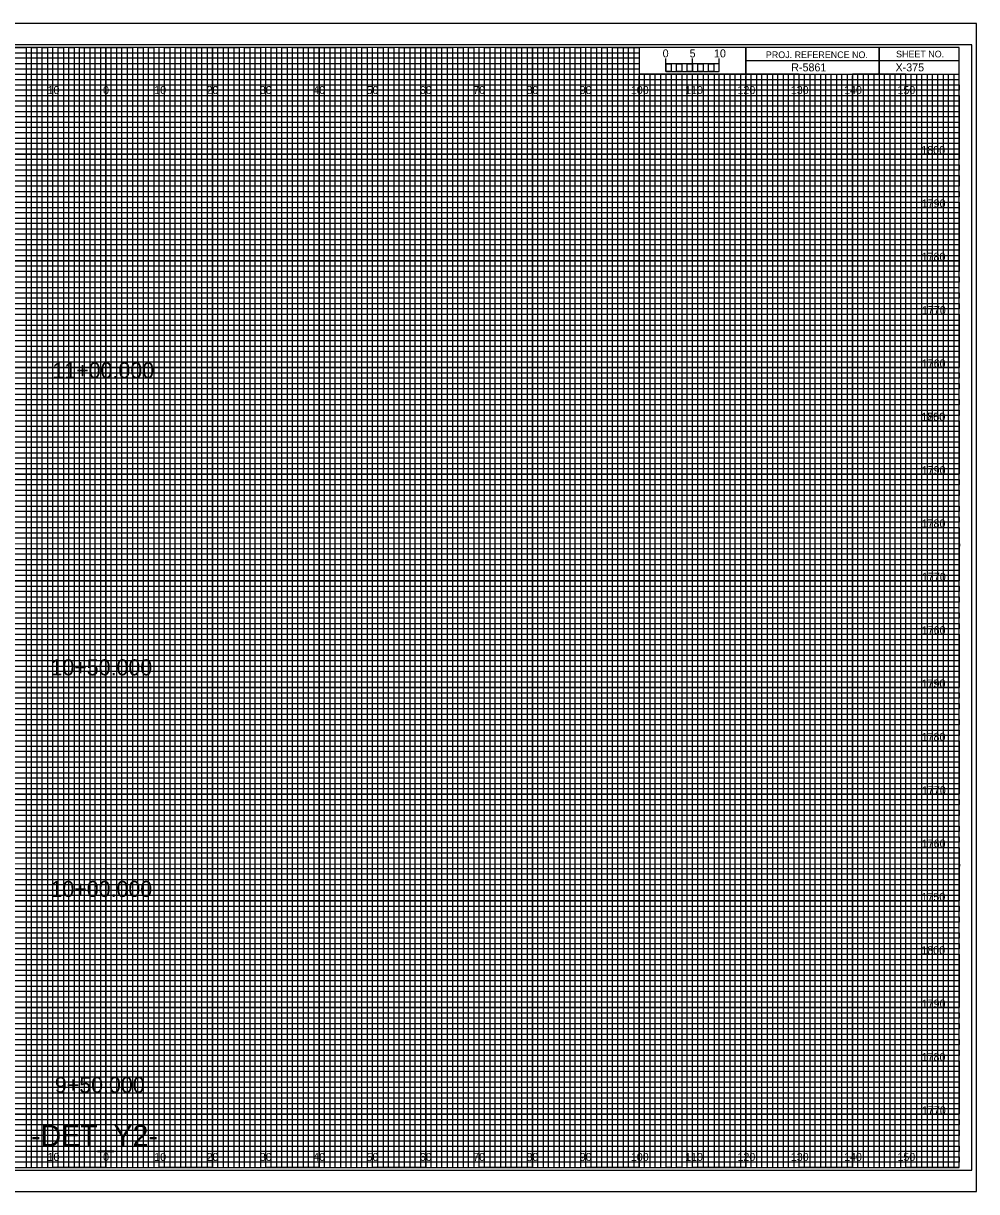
# Model space of a CAD drawing. Extents: x -13 to 323, y -5 to 874.
# Drawn here: x 144.5 to 323.3, y -4.5 to 214.5 of the extents above; entities that cross this region are included whole.
import ezdxf

# ---------------------------------------------------------------- set-up
doc = ezdxf.new("R2010")
doc.units = 0
for name, color, linetype in [('Prop Horizontal Alignment', 7, 'Continuous'), ('Prop XS Alignment Label', 7, 'Continuous'), ('Prop XS Bar Scale Labels', 7, 'Continuous'), ('Prop XS Earthwork Shape', 7, 'Continuous'), ('Prop XS Project Number', 7, 'Continuous'), ('Prop XS Sheet Number', 7, 'Continuous'), ('Raster_Level_0', 7, 'Continuous'), ('Scratch_Level_3', 7, 'Continuous'), ('Sheet Cross Section CELL', 7, 'Continuous'), ('Sheet Cross Section Grid Middle CELL', 7, 'Continuous'), ('Sheet Cross Section Grid Minor 1 CELL', 7, 'Continuous'), ('Sheet Cross Section Grid Minor 2 CELL', 7, 'Continuous'), ('Sheet Cross Section Scale CELL', 7, 'Continuous'), ('Sheet Cutting Line CELL', 7, 'Continuous'), ('Sheet DOT Grid CELL', 7, 'Continuous'), ('Sheet Plot Border Inside CELL', 7, 'Continuous'), ('Sheet Plot Border Outside CELL', 7, 'Continuous')]:
    doc.layers.add(name, color=color, linetype=linetype)

msp = doc.modelspace()

# ---------------------------------------------------------------- linework, layer by layer
at = {"layer": 'Prop XS Earthwork Shape'}
for p, q in [((150, 210), (140, 210)), ((150, 0), (150, 210)), ((170, 210), (160, 210)), ((160, 210), (160, 0)), ((170, 0), (170, 210)), ((190, 210), (180, 210)), ((180, 210), (180, 0)), ((190, 0), (190, 210)), ((210, 210), (200, 210)), ((200, 210), (200, 0)), ((210, 0), (210, 210)), ((230, 210), (220, 210)), ((220, 210), (220, 0)), ((230, 0), (230, 210)), ((250, 210), (240, 210)), ((240, 210), (240, 0)), ((250, 0), (250, 210)), ((260, 210), (260, 0)), ((270, 0), (270, 205)), ((290, 205), (280, 205)), ((280, 205), (280, 0)), ((290, 0), (290, 205)), ((310, 205), (300, 205)), ((300, 205), (300, 0)), ((310, 0), (310, 205)), ((160, 0), (150, 0)), ((180, 0), (170, 0)), ((200, 0), (190, 0)), ((220, 0), (210, 0)), ((240, 0), (230, 0)), ((260, 0), (250, 0)), ((280, 0), (270, 0)), ((300, 0), (290, 0)), ((320, 0), (310, 0)), ((320, 0), (320, 0))]:
    msp.add_line(p, q, dxfattribs=at)
for points in [[(0, 200), (320, 200), (320, 190), (0, 190)], [(0, 180), (320, 180), (320, 170), (0, 170)], [(0, 160), (320, 160), (320, 150), (0, 150)], [(0, 140), (320, 140), (320, 130), (0, 130)], [(0, 120), (320, 120), (320, 110), (0, 110)], [(0, 100), (320, 100), (320, 90), (0, 90)], [(0, 80), (320, 80), (320, 70), (0, 70)], [(0, 60), (320, 60), (320, 50), (0, 50)], [(0, 40), (320, 40), (320, 30), (0, 30)], [(0, 20), (320, 20), (320, 10), (0, 10)]]:
    msp.add_lwpolyline(points, dxfattribs=at)
at = {"layer": 'Sheet Cross Section CELL'}
for p, q in [((305, 210), (305, 205)), ((305, 205), (305, 210)), ((280, 207.5), (280, 205)), ((320, 207.49), (280, 207.49)), ((280, 205), (320, 205))]:
    msp.add_line(p, q, dxfattribs=at)
for points in [[(320, 210), (0, 210), (0, 0), (320, 0)], [(280, 210), (260, 210), (260, 205.03), (280, 205.03)], [(320, 210), (280, 210), (280, 205), (320, 205)]]:
    msp.add_lwpolyline(points, close=True, dxfattribs=at)
at = {"layer": 'Sheet Cross Section Grid Middle CELL'}
for points in [[(135, 210), (145, 210), (145, 0), (155, 0), (155, 210), (165, 210), (165, 0), (175, 0), (175, 210), (185, 210), (185, 0), (195, 0), (195, 210), (205, 210), (205, 0), (215, 0), (215, 210), (225, 210), (225, 0), (235, 0), (235, 210), (245, 210), (245, 0), (255, 0), (255, 210), (259.93, 210), (260, 210), (260, 205), (264.99, 205), (264.99, 0), (275, 0), (275, 205), (285, 205), (285, 0), (295, 0), (295, 205), (305, 205), (305, 0), (315, 0), (315, 205)], [(0, 205), (275, 205)], [(0, 185), (320, 185), (320, 195), (0, 195)], [(0, 165), (320, 165), (320, 175), (0, 175)], [(0, 145), (320, 145), (320, 155), (0, 155)], [(0, 125), (320, 125), (320, 135), (0, 135)], [(0, 105), (320, 105), (320, 115), (0, 115)], [(0, 85), (320, 85), (320, 95), (0, 95)], [(0, 65), (320, 65), (320, 75), (0, 75)], [(0, 45), (320, 45), (320, 55), (0, 55)], [(0, 25), (320, 25), (320, 35), (0, 35)], [(0, 5), (320, 5), (320, 15), (0, 15)]]:
    msp.add_lwpolyline(points, dxfattribs=at)
at = {"layer": 'Sheet Cross Section Grid Minor 1 CELL'}
for p, q in [((0, 209), (260, 209)), ((260, 209), (260, 207.98)), ((260, 207.98), (0, 207.98)), ((0, 207), (260, 207)), ((260, 205.89), (0, 205.89)), ((260, 207), (260, 205.89)), ((0, 204), (320, 204))]:
    msp.add_line(p, q, dxfattribs=at)
for points in [[(0, 203), (270, 203), (320, 203), (320, 202), (0, 202)], [(0, 201), (320, 201), (320, 199), (0, 199)], [(0, 198), (320, 198), (320, 197), (0, 196.98)], [(0, 196), (320, 196), (320, 194), (0, 194)], [(0, 193), (320, 193), (320, 192), (0, 192)], [(0, 191), (320, 191), (320, 189), (0, 189)], [(0, 188), (320, 188), (320, 187), (0, 187)], [(0, 186), (320, 186), (320, 184), (0, 184)], [(0, 183), (320, 183), (320, 182), (0, 182)], [(0, 181), (320, 181), (320, 179), (0, 179)], [(0, 178), (320, 178), (320, 177), (0, 177)], [(0, 176), (320, 176), (320, 173.95), (320, 173), (320, 172), (0, 172)], [(0, 174), (320, 174), (320, 173), (0, 173)], [(0, 171), (320, 171), (320, 169), (0, 169.03)], [(0, 169.03), (320, 169), (320, 168), (0, 168)], [(0, 167), (320, 167), (320, 166), (0, 166)], [(0, 164), (320, 164), (320, 163), (0, 163)], [(0, 162), (320, 162), (320, 161), (0, 161)], [(-0.07, 158.89), (320, 158.89), (320, 157.88), (-0.07, 157.88)], [(0, 157), (320, 157), (320, 156), (0, 156)], [(0, 154), (320, 154), (320, 153), (0, 153)], [(0, 152), (320, 152), (320, 151), (0, 151)], [(0, 149), (320, 149), (320, 148), (0, 148)], [(0, 147), (320, 147), (320, 146), (0, 146)], [(0, 144), (320, 144), (320, 143), (0, 143)], [(0, 142), (320, 142), (320, 141), (0, 141)], [(0, 139), (320, 139), (319.99, 137.98), (0, 138)], [(0, 137), (320, 137), (320, 136), (0, 136)], [(0, 134), (320, 134), (320, 133), (0, 133)], [(0, 132), (320, 132), (320, 131), (0, 131)], [(0, 129), (320, 129), (320, 128), (0, 128)], [(0, 127), (320, 127), (320, 126), (0, 126)], [(0, 124), (320, 124), (320, 123), (0, 123)], [(0, 122), (320, 122), (320, 121), (0, 121)], [(0, 119), (320, 119), (320, 118), (0, 118)], [(0, 116.99), (320.07, 116.91), (320, 116), (0, 116)], [(0, 114), (320, 114), (320, 113), (0, 113)], [(0, 112), (320, 112), (320, 111), (0, 111)], [(0, 109), (320, 109), (320, 108), (0, 108)], [(0, 107), (320, 107), (320, 106), (0, 106)], [(0, 104), (320, 104), (320, 103), (0, 103)], [(0, 102), (320, 102), (320, 101), (0, 101)], [(0, 99), (320, 99), (320, 98), (0, 98)], [(0, 97), (320, 97), (320, 96), (0, 96)], [(0, 94), (320, 94), (320, 93), (0, 93)], [(0, 92), (320, 92), (320, 91), (0, 91)], [(0, 89), (320, 89), (320, 88), (0, 88)], [(0, 87), (320, 87), (320, 86), (0, 86)], [(0, 84), (320, 84), (320, 83), (0, 83)], [(0, 82), (320, 82), (320, 81), (0, 81)], [(0, 79), (320, 79), (319.99, 77.98), (0, 78)], [(0, 77), (320, 77), (320, 76), (0, 76)], [(0, 74), (320, 74), (320, 73), (0, 73)], [(0, 72), (320, 72), (320, 71), (0, 71)], [(0, 69), (320, 69), (320, 68), (0, 68)], [(0, 67), (320, 67), (320, 66), (0, 66)], [(0, 64), (320, 64), (320, 63), (0, 63)], [(0, 62), (320, 62), (320, 61), (0, 61)], [(0, 59), (320, 59), (320, 58), (0, 58)], [(0, 56.99), (320.07, 56.91), (320, 56), (0, 56)], [(0, 54), (320, 54), (320, 53), (0, 53)], [(0, 52), (320, 52), (320, 51), (0, 51)], [(0, 49), (320, 49), (320, 48), (0, 48)], [(0, 47), (320, 47), (320, 46), (0, 46)], [(0, 44), (320, 44), (320, 43), (0, 43)], [(0, 42), (320, 42), (320, 41), (0, 41)], [(0, 39), (320, 39), (320, 38), (0, 38)], [(0, 37), (320, 37), (320, 36), (0, 36)], [(0, 34), (320, 34), (320, 33), (0, 33)], [(0, 32), (320, 32), (320, 31), (0, 31)], [(0, 29), (320, 29), (320, 28), (0, 28)], [(0, 27), (320, 27), (320, 26), (0, 26)], [(0, 24), (320, 24), (320, 23), (0, 23)], [(0, 22), (320, 22), (320, 21), (0, 21)], [(0, 19), (320, 19), (320, 18), (0, 18)], [(0, 17), (320, 17), (320, 16), (0, 16)], [(0, 14), (320, 14), (320, 13), (0, 13)], [(0, 12), (320, 12), (320, 11), (0, 11)], [(0, 9), (320, 9), (320, 8), (0, 8)], [(0, 7), (320, 7), (320, 6), (0, 6)], [(0, 4), (320, 4), (320, 3), (0, 3)], [(0, 2), (320, 2), (320, 1), (0, 1)]]:
    msp.add_lwpolyline(points, dxfattribs=at)
at = {"layer": 'Sheet Cross Section Grid Minor 2 CELL'}
for p, q in [((267, 205), (266.01, 205)), ((266.01, 205), (266.01, 0)), ((267, 0), (267, 205)), ((269, 205), (268, 205)), ((268, 205), (268, 0)), ((269, 0), (269, 205)), ((266.01, 0), (265, 0)), ((268, 0), (267, 0))]:
    msp.add_line(p, q, dxfattribs=at)
for points in [[(145, 0), (146, 0), (146, 210), (147, 210), (147, 0)], [(147, 0), (148, 0), (148, 210), (149, 210), (149, 0)], [(150, 0), (151, 0), (151, 210), (152, 210), (152, 0)], [(152, 0), (153, 0), (153, 210), (154, 210), (154, 0)], [(155, 0), (156, 0), (156, 210), (157, 210), (157, 0)], [(157, 0), (158, 0), (158, 210), (159, 210), (159, 0)], [(160, 0), (161, 0), (161, 210), (162, 210), (162, 0)], [(162, 0), (163, 0), (163, 210), (164, 210), (164, 0)], [(165, 0), (166, 0), (166, 210), (167, 210), (167, 0)], [(167, 0), (168, 0), (168, 210), (169, 210), (169, 0)], [(170, 0), (171, 0), (171, 210), (172, 210), (172, 0)], [(172, 0), (173, 0), (173, 210), (174, 210), (174, 0)], [(175, 0), (176, 0), (176, 210), (177, 210), (177, 0)], [(177, 0), (178, 0), (178, 210), (179, 210), (179, 0)], [(180, 0), (181, 0), (181, 210), (182, 210), (182, 0)], [(182, 0), (183, 0), (183, 210), (184, 210), (184, 0)], [(185, 0), (186, 0), (186, 210), (187, 210), (187, 0)], [(187, 0), (188, 0), (188, 210), (189, 210), (189, 0)], [(190, 0), (191, 0), (191, 210), (192, 210), (192, 0)], [(192, 0), (193, 0), (193, 210), (194, 210), (194, 0)], [(195, 0), (196, 0), (196, 210), (197, 210), (197, 0)], [(197, 0), (198, 0), (198, 210), (199, 210), (199, 0)], [(200, 0), (201, 0), (201, 210), (202, 210), (202, 0)], [(202, 0), (203, 0), (203, 210), (204, 210), (204, 0)], [(205, 0), (206, 0), (206, 210), (207, 210), (207, 0)], [(207, 0), (208, 0), (208, 210), (209, 210), (209, 0)], [(210, 0), (211, 0), (211, 210), (212, 210), (212, 0)], [(212, 0), (213, 0), (213, 210), (214, 210), (214, 0)], [(215, 0), (216, 0), (216, 210), (217, 210), (217, 0)], [(217, 0), (218, 0), (218, 210), (219, 210), (219, 0)], [(220, 0), (221, 0), (221, 210), (222, 210), (222, 0)], [(222, 0), (223, 0), (223, 210), (224, 210), (224, 0)], [(225, 0), (226, 0), (226, 210), (227, 210), (227, 0)], [(227, 0), (228, 0), (228, 210), (229, 210), (229, 0)], [(230, 0), (231, 0), (231, 210), (232, 210), (232, 0)], [(232, 0), (233, 0), (233, 210), (234, 210), (234, 0)], [(235, 0), (236, 0), (236, 210), (237, 210), (237, 0)], [(237, 0), (238, 0), (238, 210), (239, 210), (239, 0)], [(240, 0), (241, 0), (241, 210), (242, 210), (242, 0)], [(242, 0), (243, 0), (243, 210), (244, 210), (244, 0)], [(245, 0), (246, 0), (246, 210), (247, 210), (247, 0)], [(247, 0), (248, 0), (248, 210), (249, 210), (249, 0)], [(250, 0), (251, 0), (251, 210), (252, 210), (252, 0)], [(252, 0), (253, 0), (253, 210), (254, 210), (254, 0)], [(255, 0), (256, 0), (256, 210), (257, 210), (257, 0)], [(257, 0), (258, 0), (258, 210), (259, 210), (259, 0)], [(260, 0), (261, 0), (261, 205), (262.02, 205), (262.02, 0)], [(262, 0), (263, 0), (263, 205), (263.99, 205), (263.99, 0)], [(270, 0), (270.98, 0), (270.98, 205), (272, 205), (272, 0)], [(272, 0), (273, 0), (273, 205), (274.05, 205), (274.05, 0)], [(275, 0), (276, 0), (276, 205), (277, 205), (277, 0)], [(277, 0), (278, 0), (278, 205), (279, 205), (279, 0)], [(280, 0), (281, 0), (281, 205), (282, 205), (282, 0)], [(282, 0), (283, 0), (283, 205), (284, 205), (284, 0)], [(285, 0), (286, 0), (286, 205), (287, 205), (287, 0)], [(287, 0), (288, 0), (288, 205), (289, 205), (289, 0)], [(290, 0), (291, 0), (291, 205), (292, 205), (292, 0)], [(292, 0), (293, 0), (293, 205), (294, 205), (294, 0)], [(295, 0), (296, 0), (296, 205), (297, 205), (297, 0)], [(297, 0), (298, 0), (298, 205), (299, 205), (299, 0)], [(300, 0), (301, 0), (301, 205), (302, 205), (302, 0)], [(302, 0), (303, 0), (303, 205), (304, 205), (304, 0)], [(305, 0), (306, 0), (306, 205), (307, 205), (307, 0)], [(307, 0), (308, 0), (308, 205), (309, 205), (309, 0)], [(310, 0), (311, 0), (311, 205), (312, 205), (312, 0)], [(312, 0), (313, 0), (313, 205), (314, 205), (314, 0)], [(315, 0), (316, 0), (316, 205), (317, 205), (317, 0)], [(317, 0), (318, 0), (318, 205), (319, 205), (319, 0)]]:
    msp.add_lwpolyline(points, dxfattribs=at)
at = {"layer": 'Sheet Cross Section Scale CELL'}
for p, q in [((265, 205.49), (265, 207.9)), ((265, 206.9), (265, 207.9)), ((270, 205.49), (270, 207.9)), ((275, 205.49), (275, 207.9)), ((275, 206.9), (275, 207.9))]:
    msp.add_line(p, q, dxfattribs=at)
for points in [[(275, 206.9), (265, 206.9), (265, 205.49), (275, 205.49)], [(265, 206.9), (266, 206.9), (266, 205.49), (265, 205.49)], [(267, 206.9), (268, 206.9), (268, 205.49), (267, 205.49)], [(269, 206.9), (270, 206.9), (270, 205.49), (269, 205.49)], [(271, 206.9), (272, 206.9), (272, 205.49), (271, 205.49)], [(273, 206.9), (274, 206.9), (274, 205.49), (273, 205.49)]]:
    msp.add_lwpolyline(points, close=True, dxfattribs=at)
at = {"layer": 'Sheet Cutting Line CELL'}
for p, q in [((323.3, 214.5), (-13.4, 214.5)), ((-13.4, -4.5), (323.3, -4.5))]:
    msp.add_line(p, q, dxfattribs=at)
at = {"layer": 'Sheet DOT Grid CELL'}
for p, q in [((150, 0), (150, 210)), ((160, 0), (160, 210)), ((170, 0), (170, 210)), ((180, 0), (180, 210)), ((190, 0), (190, 210)), ((200, 0), (200, 210)), ((210, 0), (210, 210)), ((220, 0), (220, 210)), ((230, 0), (230, 210)), ((240, 0), (240, 210)), ((250, 0), (250, 210)), ((260, 0), (260, 204.69)), ((270, 0), (270, 204.69)), ((280, 0), (280, 204.69)), ((290, 0), (290, 204.69)), ((300, 0), (300, 204.69)), ((310, 0), (310, 204.69)), ((0, 200), (320, 200)), ((0, 190), (320, 190)), ((0, 180), (320, 180)), ((0, 170), (320, 170)), ((0, 160), (320, 160)), ((0, 150), (320, 150)), ((0, 140), (320, 140)), ((0, 130), (320, 130)), ((0, 120), (320, 120)), ((0, 110), (320, 110)), ((0, 100), (320, 100)), ((0, 90), (320, 90)), ((0, 80), (320, 80)), ((0, 70), (320, 70)), ((0, 60), (320, 60)), ((0, 50), (320, 50)), ((0, 40), (320, 40)), ((0, 30), (320, 30)), ((0, 20), (320, 20)), ((0, 10), (320, 10))]:
    msp.add_line(p, q, dxfattribs=at)
at = {"layer": 'Sheet Plot Border Inside CELL'}
msp.add_lwpolyline([(-10.8, -0.5), (322.4, -0.5), (322.4, 210.5), (-10.8, 210.5)], close=True, dxfattribs=at)
at = {"layer": 'Sheet Plot Border Outside CELL'}
msp.add_lwpolyline([(-13.4, -4.5), (323.3, -4.5), (323.3, 214.5), (-13.4, 214.5)], close=True, dxfattribs=at)

# ---------------------------------------------------------------- texts
at = {"layer": 'Prop Horizontal Alignment'}
for s, p in [('11+00.000', (149.95, 147.96)), ('10+50.000', (149.59, 92.28)), ('10+00.000', (149.59, 50.74)), ('9+50.000', (150.41, 14.02))]:
    msp.add_text(s, height=3, dxfattribs=at).set_placement(p)
at = {"layer": 'Prop XS Alignment Label'}
msp.add_text('-DET_Y2-', height=4, dxfattribs=at).set_placement((145.96, 4))
at = {"layer": 'Prop XS Bar Scale Labels'}
for s, p in [('5', (269.47, 208.12)), ('10', (274.04, 208.12))]:
    msp.add_text(s, height=1.5, dxfattribs=at).set_placement(p)
at = {"layer": 'Prop XS Project Number'}
msp.add_text('R-5861', height=1.5, dxfattribs=at).set_placement((288.53, 205.5))
at = {"layer": 'Prop XS Sheet Number'}
msp.add_text('X-375', height=1.5, dxfattribs=at).set_placement((308.09, 205.5))
at = {"layer": 'Raster_Level_0'}
for s, p in [('10', (149.04, 201.25)), ('0', (159.45, 201.25)), ('0', (159.45, 201.25)), ('10', (169.04, 201.25)), ('20', (178.86, 201.25)), ('30', (188.86, 201.25)), ('40', (198.86, 201.25)), ('50', (208.86, 201.25)), ('60', (218.86, 201.25)), ('70', (228.86, 201.25)), ('80', (238.86, 201.25)), ('90', (248.86, 201.25)), ('100', (258.44, 201.25)), ('110', (268.62, 201.25)), ('120', (278.44, 201.25)), ('130', (288.44, 201.25)), ('140', (298.44, 201.25)), ('150', (308.44, 201.25)), ('10', (149.04, 1.25)), ('0', (159.45, 1.25)), ('0', (159.45, 1.25)), ('10', (169.04, 1.25)), ('20', (178.86, 1.25)), ('30', (188.86, 1.25)), ('40', (198.86, 1.25)), ('50', (208.86, 1.25)), ('60', (218.86, 1.25)), ('70', (228.86, 1.25)), ('80', (238.86, 1.25)), ('90', (248.86, 1.25)), ('100', (258.44, 1.25)), ('110', (268.62, 1.25)), ('120', (278.44, 1.25)), ('130', (288.44, 1.25)), ('140', (298.44, 1.25)), ('150', (308.44, 1.25))]:
    msp.add_text(s, height=1.5, dxfattribs=at).set_placement(p)
at = {"layer": 'Scratch_Level_3'}
for s, p in [('1800', (312.92, 190)), ('1790', (313, 180)), ('1780', (312.98, 170)), ('1770', (313.04, 160)), ('1760', (313, 150)), ('1800', (312.92, 140)), ('1750', (312.96, 140)), ('1790', (313, 130)), ('1780', (312.98, 120)), ('1770', (313.04, 110)), ('1760', (313, 100)), ('1750', (312.96, 90)), ('1790', (313, 90)), ('1780', (312.98, 80)), ('1770', (313.04, 70)), ('1760', (313, 60)), ('1750', (312.96, 50)), ('1800', (312.92, 40)), ('1790', (313, 30)), ('1780', (312.98, 20)), ('1770', (313.04, 10))]:
    msp.add_text(s, height=1.5, dxfattribs=at).set_placement(p)
at = {"layer": 'Sheet Cross Section CELL'}
for s, p in [('PROJ. REFERENCE NO.', (283.77, 207.99)), ('SHEET NO.', (308.19, 208.12))]:
    msp.add_text(s, height=1.25, dxfattribs=at).set_placement(p)
at = {"layer": 'Sheet Cross Section Scale CELL'}
msp.add_text('0', height=1.5, dxfattribs=at).set_placement((264.41, 208.12))

doc.saveas('drawing.dxf')
